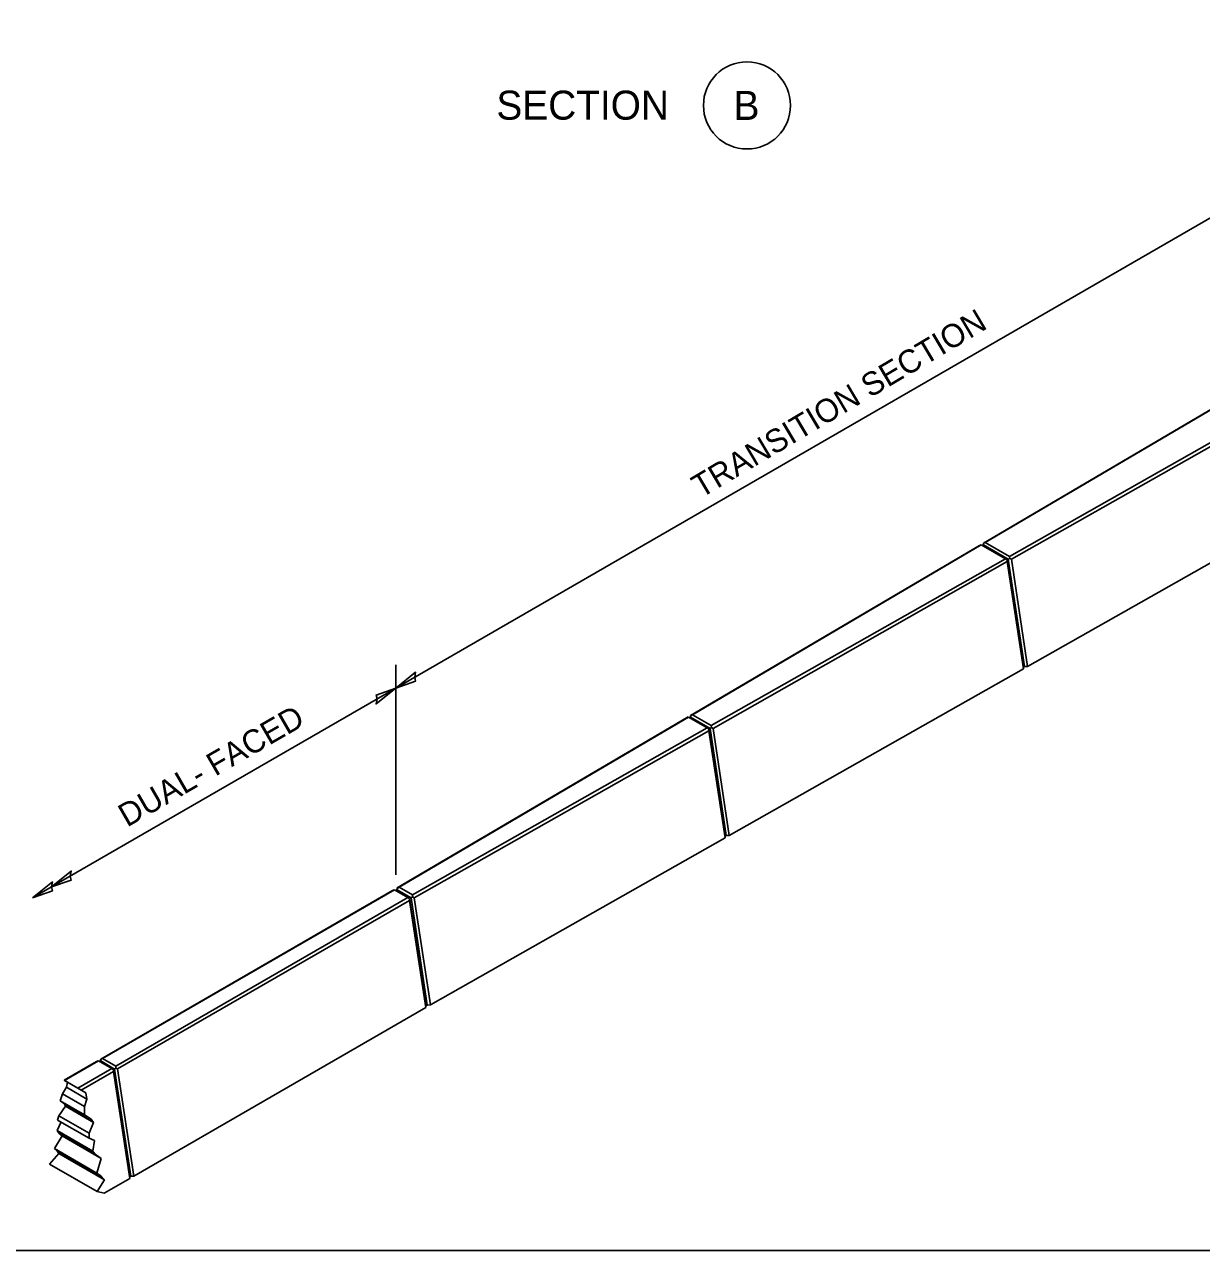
# Model space of a CAD drawing. Extents: x 99862 to 103151, y 100000 to 102076.
# Drawn here: x 100993 to 101804, y 100000 to 100844 of the extents above; entities that cross this region are included whole.
import ezdxf

# ---------------------------------------------------------------- set-up
doc = ezdxf.new("R2010")
doc.units = 0
for name, color, linetype in [('Level 1', 7, 'Continuous'), ('Level 15', 7, 'Continuous'), ('Level 2', 7, 'Continuous'), ('Level 20', 7, 'Continuous'), ('Level 3', 7, 'Continuous'), ('Level 8', 7, 'Continuous'), ('Level 9', 7, 'Continuous')]:
    doc.layers.add(name, color=color, linetype=linetype)

msp = doc.modelspace()

# ---------------------------------------------------------------- linework, layer by layer
at = {"layer": 'Level 1'}
msp.add_lwpolyline([(99862, 99999.5), (103151, 99999.5), (103151, 102075.5), (99862, 102075.5)], close=True, dxfattribs=at)
at = {"layer": 'Level 15'}
for p, q in [((101857.32, 100738.42), (101248.69, 100386.97)), ((101248.69, 100258.41), (101248.69, 100402.97)), ((101248.69, 100386.97), (100998.39, 100242.44))]:
    msp.add_line(p, q, dxfattribs=at)
at = {"layer": 'Level 2'}
for p, q in [((101683.91, 100401.9), (101886.94, 100516.97)), ((101478.38, 100285.41), (101681.06, 100400.28)), ((101272.49, 100168.72), (101475.52, 100283.79)), ((101045.3, 100131.3), (101246.47, 100247.45)), ((101046.56, 100131.78), (101247.73, 100247.93)), ((101247.62, 100247.99), (101246.47, 100247.45)), ((101247.73, 100247.93), (101256.92, 100242.62)), ((101248.61, 100247.42), (101249.67, 100248.03)), ((101055.75, 100126.47), (101256.92, 100242.62)), ((101057.01, 100124.54), (101258.18, 100240.69)), ((101258.07, 100241.96), (101256.92, 100242.62)), ((101258.18, 100240.69), (101258.07, 100241.96)), ((101269.3, 100168), (101258.17, 100241.9)), ((101258.18, 100240.69), (101269.3, 100166.89)), ((101269.3, 100166.89), (101269.3, 100168)), ((101068.12, 100050.74), (101269.3, 100166.89)), ((101042.47, 100129.67), (101020.13, 100116.78)), ((101043.73, 100130.15), (101020.35, 100116.65)), ((101052.92, 100124.84), (101029.55, 100111.34)), ((101043.62, 100130.21), (101042.47, 100129.67)), ((101052.92, 100124.84), (101043.73, 100130.15)), ((101045.31, 100130.05), (101044.61, 100129.64)), ((101045.3, 100131.3), (101045.04, 100129.89)), ((101045.41, 100131.24), (101045.31, 100130.05)), ((101045.31, 100130.05), (101054.87, 100124.53)), ((101046.56, 100131.78), (101045.41, 100131.24)), ((101055.75, 100126.47), (101046.56, 100131.78)), ((101054.07, 100124.18), (101052.92, 100124.84)), ((101055.86, 100125.21), (101054.87, 100124.53)), ((101055.86, 100125.21), (101055.75, 100126.47)), ((101057.01, 100124.54), (101055.86, 100125.21)), ((101020.13, 100116.78), (101022.4, 100115.46)), ((101020.35, 100116.65), (101020.13, 100116.78)), ((101029.55, 100111.34), (101020.35, 100116.65)), ((101054.18, 100122.91), (101031.84, 100110.01)), ((101054.07, 100124.18), (101054.17, 100124.12)), ((101054.18, 100122.91), (101054.07, 100124.18)), ((101054.87, 100124.53), (101054.17, 100124.12)), ((101054.17, 100124.12), (101065.28, 100050.35)), ((101065.3, 100049.11), (101054.18, 100122.91)), ((101054.87, 100124.53), (101065.98, 100050.75)), ((101068.12, 100050.74), (101057.01, 100124.54)), ((101021.76, 100111.92), (101018.93, 100107.47)), ((101022.4, 100115.46), (101021.76, 100111.92)), ((101035.83, 100103.79), (101021.76, 100111.92)), ((101035.18, 100108.08), (101022.4, 100115.46)), ((101031.84, 100110.01), (101029.55, 100111.34)), ((101035.18, 100108.08), (101031.84, 100110.01)), ((101035.83, 100103.79), (101035.18, 100108.08)), ((101018.93, 100107.47), (101017.39, 100102.71)), ((101017.39, 100102.71), (101020.36, 100100.55)), ((101034.19, 100093.01), (101017.39, 100102.71)), ((101034.15, 100098.68), (101018.93, 100107.47)), ((101020.36, 100100.55), (101021.05, 100098.84)), ((101038.73, 100089.94), (101020.36, 100100.55)), ((101034.15, 100098.68), (101035.83, 100103.79)), ((101016.51, 100092.34), (101015.63, 100089.37)), ((101021.05, 100098.84), (101016.51, 100092.34)), ((101037.32, 100080.33), (101016.51, 100092.34)), ((101040.29, 100087.73), (101021.05, 100098.84)), ((101034.19, 100093.01), (101034.15, 100098.68)), ((101038.73, 100089.94), (101034.19, 100093.01)), ((101017.98, 100088.02), (101015.32, 100082.16)), ((101037.45, 100076.78), (101015.63, 100089.37)), ((101037.32, 100080.33), (101040.29, 100087.73)), ((101040.29, 100087.73), (101038.73, 100089.94)), ((101018.68, 100078.46), (101013.4, 100069.78)), ((101015.32, 100082.16), (101016.63, 100080.09)), ((101040.01, 100067.9), (101015.32, 100082.16)), ((101016.63, 100080.09), (101018.68, 100078.46)), ((101042.46, 100065.18), (101016.63, 100080.09)), ((101045.67, 100062.89), (101018.68, 100078.46)), ((101037.45, 100076.78), (101037.32, 100080.33)), ((101040.96, 100075.18), (101037.45, 100076.78)), ((101040.01, 100067.9), (101040.96, 100075.18)), ((101016.46, 100066.27), (101010.11, 100059.08)), ((101013.4, 100069.78), (101015.15, 100068.33)), ((101042.68, 100052.88), (101013.4, 100069.78)), ((101015.15, 100068.33), (101016.46, 100066.27)), ((101045.44, 100050.85), (101015.15, 100068.33)), ((101047.89, 100048.12), (101016.46, 100066.27)), ((101042.46, 100065.18), (101040.01, 100067.9)), ((101042.97, 100040.11), (101010.11, 100059.08)), ((101045.67, 100062.89), (101042.46, 100065.18)), ((101042.68, 100052.88), (101045.67, 100062.89)), ((101045.44, 100050.85), (101042.68, 100052.88)), ((101047.89, 100048.12), (101045.44, 100050.85)), ((101065.3, 100049.11), (101047.74, 100038.97)), ((101065.98, 100050.75), (101065.28, 100050.35)), ((101065.28, 100050.35), (101065.3, 100049.11)), ((101065.98, 100050.75), (101068.12, 100050.74)), ((101042.97, 100040.11), (101047.89, 100048.12)), ((101047.74, 100038.97), (101042.97, 100040.11))]:
    msp.add_line(p, q, dxfattribs=at)
at = {"layer": 'Level 3'}
for p, q in [((101653.52, 100486.83), (101852.82, 100604.05)), ((101854.08, 100604.53), (101654.77, 100487.3)), ((101671.54, 100477.63), (101874.57, 100592.7)), ((101875.83, 100590.77), (101672.79, 100475.7)), ((101451.75, 100368.16), (101650.71, 100485.18)), ((101651.97, 100485.66), (101453.01, 100368.64)), ((101650.71, 100485.18), (101651.86, 100485.72)), ((101668.68, 100476.01), (101651.97, 100485.66)), ((101652.84, 100485.15), (101653.54, 100485.57)), ((101653.26, 100485.4), (101653.52, 100486.83)), ((101653.63, 100486.76), (101653.54, 100485.57)), ((101670.65, 100475.69), (101653.54, 100485.57)), ((101653.63, 100486.76), (101654.77, 100487.3)), ((101654.77, 100487.3), (101671.54, 100477.63)), ((101466, 100361.14), (101668.68, 100476.01)), ((101669.94, 100474.08), (101467.26, 100359.21)), ((101668.68, 100476.01), (101669.84, 100475.34)), ((101669.84, 100475.34), (101669.94, 100474.08)), ((101669.93, 100475.29), (101670.65, 100475.69)), ((101669.93, 100475.29), (101681.07, 100401.38)), ((101681.06, 100400.28), (101669.94, 100474.08)), ((101671.64, 100476.36), (101670.65, 100475.69)), ((101681.78, 100401.79), (101670.65, 100475.69)), ((101671.54, 100477.63), (101671.64, 100476.36)), ((101671.64, 100476.36), (101672.79, 100475.7)), ((101672.79, 100475.7), (101683.91, 100401.9)), ((101681.07, 100401.38), (101681.06, 100400.28)), ((101681.07, 100401.38), (101681.78, 100401.79)), ((101683.91, 100401.9), (101681.78, 100401.79)), ((101249.64, 100249.29), (101448.95, 100366.52)), ((101450.21, 100366.99), (101250.9, 100249.77)), ((101448.95, 100366.52), (101450.1, 100367.06)), ((101463.15, 100359.52), (101450.21, 100366.99)), ((101451.78, 100366.9), (101451.08, 100366.49)), ((101451.49, 100366.73), (101451.75, 100368.16)), ((101451.87, 100368.1), (101451.78, 100366.9)), ((101465.12, 100359.2), (101451.78, 100366.9)), ((101451.87, 100368.1), (101453.01, 100368.64)), ((101453.01, 100368.64), (101466, 100361.14)), ((101260.11, 100244.45), (101463.15, 100359.52)), ((101464.41, 100357.59), (101261.37, 100242.52)), ((101463.15, 100359.52), (101464.3, 100358.86)), ((101464.3, 100358.86), (101464.41, 100357.59)), ((101465.12, 100359.2), (101464.4, 100358.8)), ((101464.4, 100358.8), (101475.53, 100284.9)), ((101475.52, 100283.79), (101464.41, 100357.59)), ((101465.12, 100359.2), (101466.11, 100359.88)), ((101476.25, 100285.3), (101465.12, 100359.2)), ((101466, 100361.14), (101466.11, 100359.88)), ((101466.11, 100359.88), (101467.26, 100359.21)), ((101467.26, 100359.21), (101478.38, 100285.41)), ((101475.53, 100284.9), (101476.25, 100285.3)), ((101476.25, 100285.3), (101478.38, 100285.41)), ((101475.52, 100283.79), (101475.53, 100284.9)), ((101249.67, 100248.03), (101248.61, 100247.42)), ((101248.61, 100247.42), (101256.92, 100242.62)), ((101249.38, 100247.87), (101249.64, 100249.29)), ((101249.76, 100249.23), (101249.67, 100248.03)), ((101259.23, 100242.51), (101249.67, 100248.03)), ((101259.23, 100242.51), (101249.67, 100248.03)), ((101249.76, 100249.23), (101250.9, 100249.77)), ((101250.9, 100249.77), (101260.11, 100244.45)), ((101259.23, 100242.51), (101260.22, 100243.19)), ((101260.11, 100244.45), (101260.22, 100243.19)), ((101260.22, 100243.19), (101261.37, 100242.52)), ((101256.92, 100242.62), (101258.07, 100241.96)), ((101258.17, 100241.9), (101258.07, 100241.96)), ((101258.07, 100241.96), (101258.17, 100241.9)), ((101258.17, 100241.9), (101269.3, 100168)), ((101270.36, 100168.61), (101259.23, 100242.51)), ((101270.36, 100168.61), (101259.23, 100242.51)), ((101261.37, 100242.52), (101272.49, 100168.72)), ((101269.3, 100168), (101270.36, 100168.61)), ((101272.49, 100168.72), (101270.36, 100168.61))]:
    msp.add_line(p, q, dxfattribs=at)
at = {"layer": 'Level 8'}
for points in [[(101248.69, 100386.97), (101262.31, 100397.92), (101261.68, 100394.47), (101262.31, 100391.75)], [(101248.69, 100386.97), (101235.07, 100376.02), (101235.7, 100379.47), (101235.07, 100382.19)], [(101011.38, 100249.94), (101025, 100260.89), (101024.37, 100257.44), (101025, 100254.72)], [(100998.39, 100242.44), (101012.01, 100253.39), (101011.38, 100249.94), (101012.01, 100247.22)]]:
    msp.add_lwpolyline(points, close=True, dxfattribs=at)
at = {"layer": 'Level 9'}
msp.add_circle((101490.6, 100788.41), 30, dxfattribs=at)

# ---------------------------------------------------------------- texts
at = {"layer": 'Level 20'}
for s, p in [('SECTION', (101317.95, 100778.6)), ('B', (101481.36, 100778.41))]:
    msp.add_text(s, height=20, dxfattribs=at).set_placement(p)
for s, rotation, p in [('TRANSITION SECTION', 30.69362, (101458.8, 100517.47)), ('DUAL- FACED', 30, (101063.5, 100290.81))]:
    msp.add_text(s, height=16, rotation=rotation, dxfattribs=at).set_placement(p)

doc.saveas('drawing.dxf')
